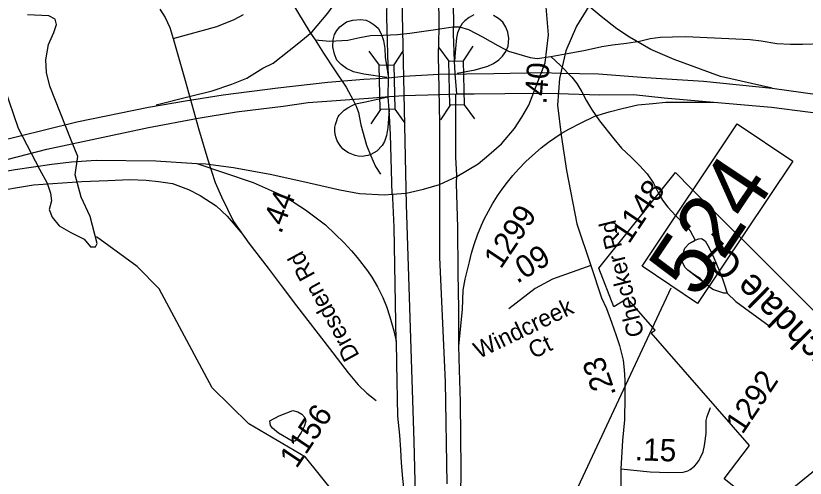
# Model space of a CAD drawing. Extents: x 1715610 to 1720914, y 798298 to 802505.
# Drawn here: x 1716117.1 to 1716213.5, y 799648.9 to 799705.3 of the extents above; entities that cross this region are included whole.
import ezdxf

# ---------------------------------------------------------------- set-up
doc = ezdxf.new("R2010")
doc.units = 0
doc.layers.add('Default', color=7, linetype='Continuous')

msp = doc.modelspace()

# ---------------------------------------------------------------- linework, layer by layer
at = {"layer": 'Default'}
for p, q in [((1716168.684, 799701.515), (1716169.944, 799699.804)), ((1716172.883, 799701.615), (1716171.707, 799699.846)), ((1716160.188, 799700.995), (1716161.448, 799699.284)), ((1716164.387, 799701.096), (1716163.21, 799699.327)), ((1716170.725, 799698.299), (1716170.654, 799699.775)), ((1716162.55, 799695.386), (1716162.593, 799697.757)), ((1716162.593, 799697.757), (1716164.433, 799697.95)), ((1716164.433, 799697.95), (1716168.752, 799698.213)), ((1716170.921, 799695.793), (1716170.725, 799698.299)), ((1716181.438, 799698.385), (1716183.597, 799698.305)), ((1716164.41, 799695.586), (1716168.827, 799695.739)), ((1716168.827, 799695.739), (1716170.921, 799695.793)), ((1716180.519, 799695.892), (1716183.294, 799695.84)), ((1716134.187, 799694.438), (1716138.249, 799695.483)), ((1716162.66, 799693.861), (1716162.55, 799695.386)), ((1716162.686, 799695.485), (1716164.41, 799695.586)), ((1716161.608, 799693.895), (1716160.432, 799692.126)), ((1716163.331, 799693.937), (1716164.591, 799692.226)), ((1716170.105, 799694.415), (1716168.928, 799692.645)), ((1716171.827, 799694.456), (1716173.087, 799692.745)), ((1716168.802, 799684.74), (1716170.911, 799685.725)), ((1716163.03, 799683.559), (1716164.745, 799683.672)), ((1716199.412, 799679.088), (1716200.039, 799677.922)), ((1716172.524, 799619.639), (1716197.08, 799672.096))]:
    msp.add_line(p, q, dxfattribs=at)
for points in [[(1716163.138, 799752.144), (1716163.591, 799739.13), (1716164.027, 799715.23), (1716164.737, 799682.293), (1716165.674, 799653.347), (1716166.054, 799638.762)], [(1716169.739, 799648.174), (1716169.534, 799660.652), (1716168.857, 799675.817), (1716168.851, 799692.218), (1716168.699, 799700.536), (1716168.767, 799703.779), (1716168.561, 799725.158), (1716168.721, 799741.305), (1716168.678, 799748.436)], [(1716170.654, 799699.775), (1716170.506, 799703.134), (1716170.559, 799704.768), (1716170.38, 799710.838), (1716170.378, 799712.39), (1716170.36, 799715.692), (1716170.316, 799721.848), (1716170.249, 799724.486), (1716170.166, 799729.053), (1716170.112, 799733.068), (1716170.143, 799734.71)], [(1716133.747, 799732.377), (1716133.848, 799731.676), (1716134.068, 799730.997), (1716134.72, 799729.868), (1716135.336, 799728.92), (1716136.384, 799727.832), (1716137.2, 799727.173), (1716138.241, 799726.46), (1716139.333, 799725.976), (1716140.378, 799725.577), (1716140.954, 799725.342), (1716141.82, 799724.757), (1716142.68, 799724.01), (1716144.442, 799721.805), (1716145.38, 799720.479), (1716146.085, 799718.891), (1716147.451, 799716.109), (1716147.927, 799715.26), (1716148.61, 799712.79), (1716149.084, 799710.782), (1716149.474, 799709.196), (1716150.778, 799706.938), (1716152.956, 799703.339), (1716153.633, 799702.403)], [(1716138.249, 799695.483), (1716141.062, 799696.16), (1716143.458, 799696.965), (1716145.264, 799697.714), (1716147.221, 799698.914), (1716148.506, 799699.559), (1716151.417, 799701.867), (1716153.199, 799703.336), (1716155.186, 799705.642), (1716156.806, 799707.929), (1716158.323, 799710.462), (1716159.801, 799713.73), (1716160.563, 799716.857), (1716161.307, 799721.149), (1716161.77, 799727.936)], [(1716162.593, 799697.757), (1716162.384, 799705.143), (1716162.403, 799707.312), (1716162.216, 799711.8), (1716162.14, 799715.433), (1716162.049, 799719.043), (1716161.974, 799723.261), (1716161.77, 799727.936)], [(1716170.911, 799685.725), (1716173.515, 799687.261), (1716174.811, 799688.348), (1716176.366, 799689.71), (1716177.98, 799691.579), (1716178.848, 799692.937), (1716179.717, 799694.416), (1716181.696, 799699.576), (1716182.131, 799703.002), (1716181.839, 799706.43), (1716181.541, 799708.088), (1716181.08, 799709.808), (1716180.327, 799711.866), (1716179.494, 799713.632), (1716178.608, 799715.233), (1716175.912, 799719.653)], [(1716194.979, 799717.112), (1716187.567, 799707.413), (1716185.545, 799704.058), (1716184.218, 799701.067), (1716183.473, 799697.688), (1716183.208, 799694.41), (1716183.672, 799690.764), (1716184.323, 799686.45), (1716185.571, 799679.926), (1716187.295, 799674.861)], [(1716209.452, 799696.487), (1716203.122, 799697.904), (1716197.448, 799699.982), (1716194.596, 799701.21), (1716192.012, 799702.736), (1716190.469, 799703.731), (1716188.535, 799705.258), (1716187.082, 799706.463)], [(1716115.688, 799696.501), (1716117.368, 799691.604), (1716119.949, 799686.593), (1716120.912, 799684.901), (1716121.279, 799683.677), (1716121.422, 799682.743), (1716121.13, 799681.681), (1716121.483, 799680.746), (1716122.366, 799679.666), (1716123.781, 799678.859), (1716125.405, 799678.051), (1716126.175, 799677.116), (1716126.803, 799677.115), (1716127.013, 799677.534), (1716126.151, 799680.835), (1716125.061, 799683.172), (1716124.31, 799685.91), (1716124.621, 799688.147), (1716123.804, 799690.161), (1716121.21, 799696.717), (1716120.795, 799698.392), (1716120.733, 799699.97), (1716121.075, 799701.837), (1716121.706, 799703.301), (1716122.014, 799704.283), (1716121.886, 799704.927), (1716121.098, 799705.315), (1716118.475, 799705.464)], [(1716134.659, 799706.153), (1716135.308, 799705.131), (1716135.868, 799703.896), (1716136.262, 799702.545)], [(1716136.262, 799702.545), (1716141.629, 799704.027), (1716143.743, 799704.877), (1716144.887, 799705.471)], [(1716172.986, 799705.46), (1716172.438, 799705.14), (1716171.89, 799704.702), (1716171.563, 799704.39), (1716171.241, 799703.82), (1716171.013, 799703.246), (1716170.872, 799702.653), (1716170.756, 799701.336), (1716170.654, 799699.775)], [(1716162.393, 799697.81), (1716159.549, 799698.183), (1716158.319, 799698.486), (1716157.457, 799698.9), (1716156.812, 799699.396), (1716156.258, 799699.93), (1716155.981, 799700.636), (1716155.765, 799701.53), (1716155.812, 799702.378), (1716155.993, 799703.038), (1716156.287, 799703.525), (1716156.648, 799703.967), (1716157.444, 799704.574), (1716158.24, 799704.79), (1716159.164, 799704.856), (1716159.839, 799704.795), (1716160.334, 799704.561), (1716160.829, 799704.23), (1716161.301, 799703.816), (1716161.69, 799703.133), (1716161.966, 799702.329), (1716162.144, 799701.331), (1716162.18, 799700.265), (1716162.593, 799697.757)], [(1716170.965, 799698.306), (1716173.18, 799698.75), (1716174.709, 799699.168), (1716175.411, 799699.499), (1716176.047, 799699.971), (1716176.498, 799700.405), (1716176.92, 799700.988), (1716177.202, 799701.6), (1716177.278, 799702.575), (1716177.151, 799703.321), (1716176.921, 799703.946), (1716176.533, 799704.54), (1716176.018, 799705.002), (1716175.417, 799705.365)], [(1716153.633, 799702.403), (1716155.419, 799702.238), (1716157.617, 799702.372), (1716159.091, 799702.678), (1716160.362, 799702.917), (1716161.98, 799702.972), (1716163.659, 799703.04), (1716165.194, 799703.203), (1716168.301, 799703.663), (1716170.427, 799703.999), (1716171.248, 799703.965), (1716172.343, 799703.64), (1716174.07, 799702.774), (1716175.93, 799701.717), (1716177.247, 799701.023), (1716179.869, 799700.234), (1716180.739, 799700.119), (1716182.383, 799700.366)], [(1716136.262, 799702.545), (1716137.733, 799697.428), (1716139.388, 799691.565), (1716140.493, 799687.738), (1716141.423, 799684.984), (1716142.163, 799683.207), (1716143.652, 799680.226), (1716145.531, 799677.584), (1716147.873, 799674.506), (1716149.451, 799672.39), (1716151.352, 799669.907), (1716155.39, 799664.693), (1716157.67, 799661.757), (1716158.856, 799660.279), (1716159.931, 799659.263), (1716161.053, 799658.37)], [(1716182.383, 799700.366), (1716184.173, 799700.67), (1716186.652, 799701.137), (1716188.636, 799701.574), (1716189.943, 799701.789), (1716191.656, 799701.984), (1716193.242, 799702.221), (1716194.524, 799702.554), (1716195.745, 799702.725), (1716197.241, 799702.754), (1716198.896, 799702.784), (1716206.761, 799702.42), (1716208.075, 799702.259), (1716210.012, 799701.934), (1716211.653, 799701.866), (1716213.126, 799701.862), (1716215.553, 799701.945), (1716216.881, 799702.037), (1716218.162, 799702.216)], [(1716153.633, 799702.403), (1716154.63, 799700.775), (1716155.982, 799698.743), (1716157.42, 799696.605), (1716158.282, 799695.014), (1716158.637, 799694.299), (1716158.904, 799693.535), (1716159.188, 799692.02), (1716159.908, 799689.525), (1716160.401, 799688.24), (1716160.991, 799686.944), (1716161.61, 799685.998)], [(1716182.383, 799700.366), (1716183.59, 799699.279), (1716184.983, 799697.847), (1716185.568, 799697.08), (1716186.172, 799696.037), (1716186.751, 799694.957), (1716187.356, 799693.914), (1716188.341, 799692.503), (1716190.101, 799690.295), (1716191.029, 799689.185), (1716192.213, 799688.065), (1716193.25, 799687.039), (1716194.156, 799686.051), (1716194.94, 799684.883), (1716195.588, 799683.596), (1716196.051, 799682.808), (1716196.683, 799681.956), (1716197.658, 799680.917), (1716198.734, 799679.869), (1716199.006, 799679.574), (1716199.412, 799679.088)], [(1716101.568, 799685.934), (1716109.045, 799688.292), (1716114.589, 799689.948), (1716120.572, 799691.399), (1716124.499, 799692.363), (1716133.284, 799694.156), (1716137.803, 799694.946), (1716142.39, 799695.668), (1716149.077, 799696.515), (1716155.15, 799697.239), (1716159.547, 799697.579), (1716162.593, 799697.757)], [(1716168.752, 799698.213), (1716175.448, 799698.299), (1716181.438, 799698.385)], [(1716183.597, 799698.305), (1716188.208, 799698.232), (1716193.991, 799697.798), (1716201.065, 799697.328), (1716209.452, 799696.487)], [(1716170.909, 799685.869), (1716170.812, 799688.017), (1716170.801, 799695.79)], [(1716170.921, 799695.793), (1716173.025, 799695.79), (1716180.519, 799695.892)], [(1716183.294, 799695.84), (1716188.376, 799695.675), (1716192.516, 799695.713), (1716196.262, 799695.313), (1716202.321, 799694.77)], [(1716209.452, 799696.487), (1716216.99, 799695.419), (1716231.7, 799693.33), (1716242.165, 799691.483)], [(1716139.343, 799692.84), (1716144.007, 799693.588), (1716149.698, 799694.294), (1716152.763, 799694.751), (1716160.142, 799695.281), (1716162.686, 799695.485)], [(1716162.66, 799693.861), (1716162.476, 799691.678), (1716162.32, 799690.73), (1716162.069, 799689.973), (1716161.803, 799689.481), (1716161.17, 799688.82), (1716160.434, 799688.388), (1716160.047, 799688.278), (1716159.362, 799688.169), (1716158.891, 799688.199), (1716158.503, 799688.287), (1716158.1, 799688.419), (1716157.685, 799688.61), (1716157.366, 799688.79), (1716157.053, 799689.042), (1716156.748, 799689.384), (1716156.498, 799689.732), (1716156.31, 799690.056), (1716156.182, 799690.444), (1716156.083, 799690.837), (1716156.03, 799691.286), (1716156.031, 799691.724), (1716156.111, 799692.076), (1716156.251, 799692.542), (1716156.353, 799692.81), (1716156.431, 799692.99), (1716156.564, 799693.177), (1716156.902, 799693.553), (1716157.165, 799693.791), (1716157.624, 799694.104), (1716158.127, 799694.379), (1716158.552, 799694.577), (1716159.782, 799694.825), (1716162.686, 799695.485)], [(1716183.672, 799690.941), (1716184.591, 799691.471), (1716186.025, 799692.202), (1716187.788, 799693.085), (1716189.54, 799693.584), (1716191.133, 799694.009), (1716193.027, 799694.449), (1716194.863, 799694.639), (1716196.446, 799694.778), (1716202.321, 799694.77)], [(1716202.321, 799694.77), (1716209.351, 799694.179), (1716218.23, 799693.053), (1716228.08, 799691.578), (1716237.075, 799690.174), (1716241.606, 799689.448)], [(1716163.03, 799683.559), (1716162.833, 799690.855), (1716162.66, 799693.861)], [(1716074.256, 799668.3), (1716076.8, 799670.4), (1716078.369, 799671.626), (1716080.001, 799672.794), (1716083.358, 799674.942), (1716086.42, 799676.775), (1716088.429, 799677.991), (1716090.24, 799678.912), (1716093.97, 799680.666), (1716098.849, 799682.602), (1716104.155, 799684.484), (1716111.353, 799686.603), (1716120.844, 799689.037), (1716133.266, 799691.705), (1716139.343, 799692.84)], [(1716171.162, 799665.03), (1716171.613, 799669.478), (1716171.7, 799671.818), (1716171.949, 799673.181), (1716172.482, 799675.274), (1716172.694, 799676.332), (1716173.027, 799677.399), (1716173.432, 799678.601), (1716173.941, 799679.769), (1716174.252, 799680.506), (1716174.786, 799681.493), (1716175.278, 799682.364), (1716175.899, 799683.347), (1716176.471, 799684.146), (1716177.092, 799685.021), (1716177.756, 799685.849), (1716178.465, 799686.61), (1716179.347, 799687.547), (1716180.148, 799688.283), (1716181.231, 799689.194), (1716182.128, 799689.884), (1716183.672, 799690.941)], [(1716099.73, 799682.616), (1716109.869, 799685.306), (1716116.993, 799686.565), (1716121.47, 799687.225), (1716123.869, 799687.511), (1716126.892, 799687.695), (1716134.159, 799687.623), (1716139.173, 799687.294), (1716140.277, 799687.249)], [(1716139.173, 799687.294), (1716146.068, 799684.995), (1716149.348, 799683.512), (1716151.065, 799682.533), (1716152.448, 799681.63), (1716153.763, 799680.661), (1716154.883, 799679.8), (1716156.079, 799678.686), (1716157.148, 799677.614), (1716158.061, 799676.645), (1716158.76, 799675.821), (1716160.007, 799674.183), (1716160.556, 799673.436), (1716161.248, 799672.236), (1716161.904, 799670.949), (1716162.339, 799669.831), (1716162.759, 799668.591), (1716163.209, 799666.862), (1716163.515, 799665.585)], [(1716140.277, 799687.249), (1716143.648, 799686.821), (1716148.312, 799685.97), (1716152.902, 799684.915), (1716156.621, 799684.065), (1716159.048, 799683.639), (1716162.1, 799683.488), (1716163.03, 799683.559)], [(1716199.599, 799684.203), (1716222.135, 799661.739), (1716219.645, 799659.532), (1716222.609, 799656.328), (1716214.295, 799649.542), (1716208.554, 799644.84), (1716203.568, 799648.809), (1716206.645, 799652.847), (1716194.636, 799666.639), (1716195.143, 799666.928), (1716192.833, 799669.586), (1716191.755, 799670.828), (1716190.104, 799669.81), (1716188.278, 799674.507), (1716197.61, 799686.195), (1716199.599, 799684.203)], [(1716199.599, 799684.203), (1716222.135, 799661.739), (1716219.645, 799659.532), (1716222.609, 799656.328), (1716214.295, 799649.542), (1716208.554, 799644.84), (1716203.568, 799648.809), (1716206.645, 799652.847), (1716194.636, 799666.639), (1716195.143, 799666.928), (1716192.833, 799669.586), (1716191.755, 799670.828), (1716190.104, 799669.81), (1716188.278, 799674.507), (1716197.61, 799686.195), (1716199.599, 799684.203)], [(1716101.901, 799672.966), (1716102.794, 799675.696), (1716103.989, 799677.708), (1716105.779, 799679.93), (1716107.779, 799681.555), (1716110.129, 799683.022), (1716112.249, 799683.579), (1716113.844, 799683.804), (1716119.223, 799684.687), (1716125.109, 799685.079), (1716128.315, 799685.213), (1716130.978, 799685.331), (1716132.992, 799685.275), (1716134.481, 799685.115), (1716136.214, 799684.866), (1716138.14, 799684.109), (1716139.557, 799683.389), (1716141.534, 799682.141), (1716142.881, 799680.86), (1716144.541, 799678.913)], [(1716171.157, 799669.529), (1716171.102, 799673.952), (1716171.062, 799679.462), (1716170.882, 799684.845), (1716170.909, 799685.869)], [(1716164.745, 799683.672), (1716166.839, 799684.163), (1716168.802, 799684.74)], [(1716163.515, 799665.585), (1716163.273, 799679.532), (1716163.1, 799683.096), (1716163.1, 799683.481)], [(1716167.531, 799630.816), (1716161.425, 799640.269), (1716152.431, 799651.446), (1716145.523, 799655.517), (1716141.023, 799659.919), (1716134.578, 799672.003), (1716131.871, 799674.733), (1716126.907, 799678.345)], [(1716203.948, 799671.458), (1716203.539, 799671.474), (1716202.936, 799671.674), (1716202.204, 799671.912), (1716201.511, 799672.44), (1716200.637, 799673.245), (1716199.883, 799673.76), (1716199.129, 799674.276), (1716198.784, 799674.619), (1716198.429, 799675.334), (1716198.524, 799676.167), (1716198.749, 799676.961), (1716199.298, 799677.533), (1716199.952, 799677.873), (1716200.039, 799677.922)], [(1716203.948, 799671.458), (1716203.539, 799671.474), (1716202.204, 799671.912), (1716201.511, 799672.44), (1716199.129, 799674.276), (1716198.784, 799674.619), (1716198.429, 799675.334), (1716198.524, 799676.167), (1716198.749, 799676.961), (1716199.298, 799677.533), (1716200.039, 799677.922)], [(1716200.039, 799677.922), (1716200.475, 799678.098), (1716200.816, 799678.132), (1716201.246, 799677.839), (1716201.719, 799676.986), (1716202.319, 799675.784), (1716202.884, 799674.451), (1716203.366, 799673.227), (1716203.658, 799672.344), (1716203.843, 799671.69), (1716203.948, 799671.458)], [(1716200.039, 799677.922), (1716200.475, 799678.098), (1716200.816, 799678.132), (1716201.246, 799677.839), (1716201.719, 799676.986), (1716202.319, 799675.784), (1716202.884, 799674.451), (1716203.366, 799673.227), (1716203.658, 799672.344), (1716203.948, 799671.458)], [(1716187.295, 799674.861), (1716182.618, 799673.161), (1716180.473, 799672.054), (1716177.269, 799669.562)], [(1716187.295, 799674.861), (1716188.605, 799670.89), (1716189.189, 799669.589), (1716189.815, 799667.944), (1716190.389, 799666.288), (1716190.799, 799665.067), (1716191.227, 799663.284), (1716191.361, 799662.092), (1716191.442, 799660.838), (1716191.455, 799659.935), (1716191.458, 799658.794), (1716191.385, 799655.998), (1716191.165, 799653.457), (1716190.934, 799650.027)], [(1716203.948, 799671.458), (1716205.011, 799670.467), (1716208.614, 799667.798), (1716209.009, 799667.528)], [(1716171.301, 799630.938), (1716171.329, 799639.346), (1716171.455, 799650.07), (1716171.394, 799653.909), (1716171.364, 799658.206), (1716171.245, 799662.124), (1716171.162, 799665.03), (1716171.157, 799669.529)], [(1716163.515, 799665.585), (1716163.567, 799662.894), (1716163.694, 799656.448), (1716163.916, 799654.112), (1716164.041, 799652.332), (1716164.141, 799650.747), (1716164.292, 799648.838), (1716164.535, 799646.667), (1716164.737, 799644.902), (1716165.012, 799640.411), (1716165.667, 799635.189)], [(1716190.934, 799650.027), (1716194.538, 799649.648), (1716196.833, 799649.572), (1716198.547, 799649.619), (1716199.14, 799649.784), (1716199.436, 799649.954), (1716199.967, 799650.351), (1716200.214, 799650.681), (1716200.511, 799651.085), (1716200.647, 799651.319), (1716201, 799652.093), (1716201.164, 799652.868), (1716201.194, 799653.161), (1716201.354, 799654.311), (1716201.353, 799655.928), (1716201.496, 799656.407), (1716201.916, 799657.497)], [(1716150.798, 799653.402), (1716149.149, 799654.383), (1716148.415, 799654.972), (1716148.155, 799655.318), (1716148.089, 799655.878), (1716149.232, 799656.487), (1716150.896, 799657.14), (1716151.49, 799656.964), (1716151.998, 799656.698), (1716152.376, 799656.273), (1716152.466, 799655.82), (1716152.283, 799655.181), (1716151.897, 799654.458), (1716151.426, 799653.718), (1716151.149, 799653.413), (1716150.798, 799653.402)], [(1716190.934, 799650.027), (1716190.932, 799647.869), (1716191.04, 799644.157), (1716191.292, 799642.617), (1716192.084, 799639.83), (1716193.192, 799637.451), (1716195.649, 799633.348)]]:
    msp.add_lwpolyline(points, dxfattribs=at)
for points in [[(1716171.707, 799699.846), (1716171.836, 799694.456), (1716170.073, 799694.414), (1716169.944, 799699.804)], [(1716163.21, 799699.327), (1716163.339, 799693.937), (1716161.577, 799693.895), (1716161.448, 799699.284)], [(1716193.55, 799674.751), (1716205.175, 799692.119), (1716211.954, 799687.582), (1716200.329, 799670.214)]]:
    msp.add_lwpolyline(points, close=True, dxfattribs=at)

# ---------------------------------------------------------------- texts
for s, height, rotation, p in [('.40', 2.7188, 85.3947, (1716181.85, 799694.48)), ('524', 7.6125, 56.20506, (1716200.255, 799670.592)), ('1148', 2.7188, 56.20506, (1716191.942, 799677.384)), ('.44', 2.7188, 69.2145, (1716149.452, 799678.61)), ('1299', 2.7188, 56.20506, (1716176.289, 799674.311)), ('Checker Rd', 2.0663, 104.10177, (1716193.82, 799666.387)), ('Archdale CL', 3.2625, 135.20152, (1716219.137, 799662.062)), ('Dresden Rd', 2.0663, 118.76781, (1716159.08, 799663.854)), ('.09', 2.7188, 31.73469, (1716178.283, 799672.582)), ('Windcreek ', 2.0663, 25.72516, (1716173.607, 799663.418)), ('Ct', 2.0663, 25.72516, (1716180.281, 799663.406)), ('.23', 2.7188, 109.10558, (1716190.407, 799659.134)), ('1292', 2.7188, 56.20506, (1716205.799, 799654.122)), ('1156', 2.7188, 56.20506, (1716151.345, 799649.963)), ('.15', 2.7188, 358.09742, (1716192.63, 799651.072))]:
    msp.add_text(s, height=height, rotation=rotation, dxfattribs=at).set_placement(p)

doc.saveas('drawing.dxf')
